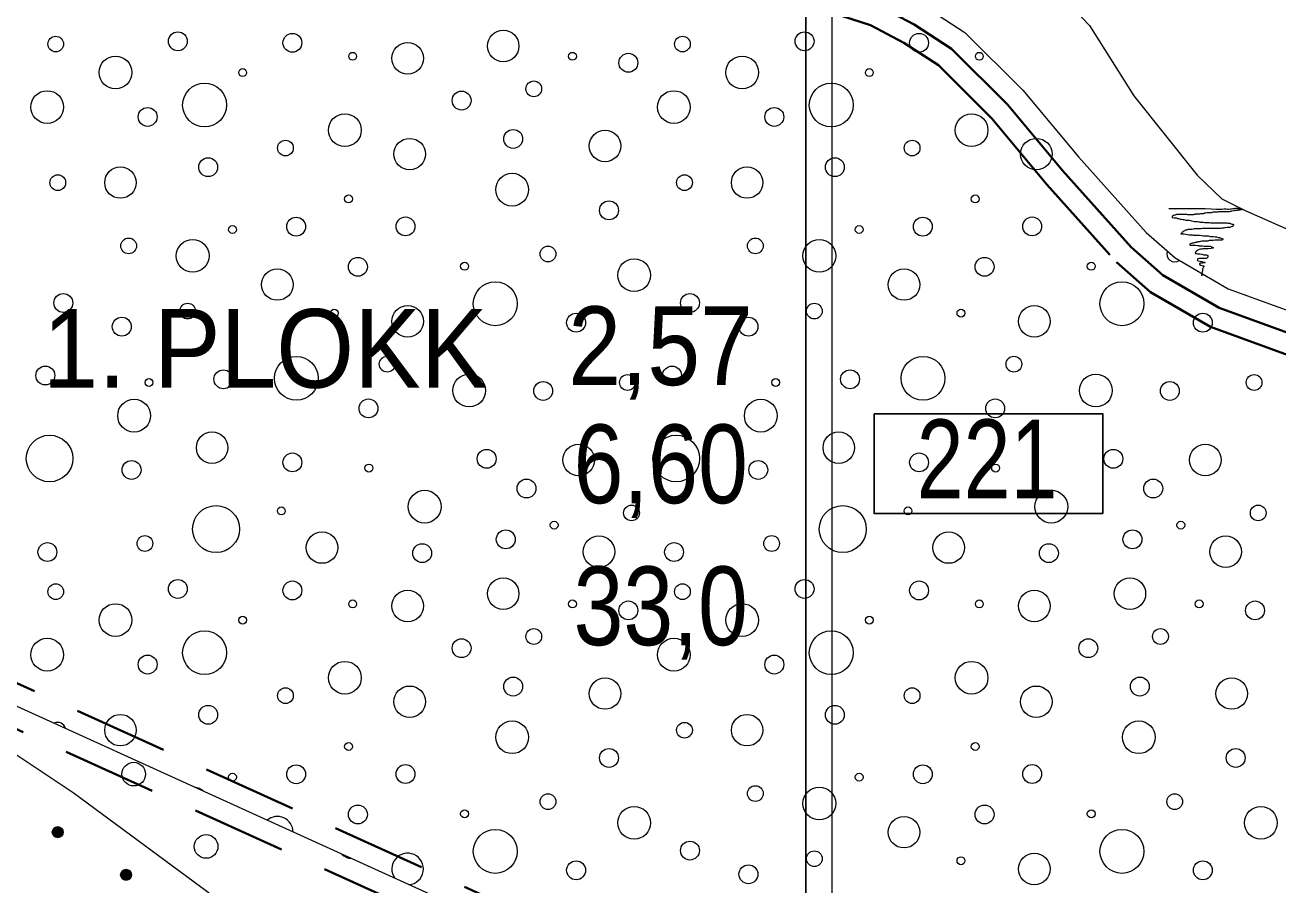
# Model space of a CAD drawing. Extents: x 640104 to 640970, y 6442278 to 6442689.
# Drawn here: x 640265.58 to 640313.3, y 6442396.62 to 6442429.39 of the extents above; entities that cross this region are included whole.
import ezdxf
from ezdxf.enums import TextEntityAlignment as Align

# ---------------------------------------------------------------- set-up
doc = ezdxf.new("R2010")
doc.units = 0
doc.header["$LTSCALE"] = 1.2
doc.linetypes.add('MEDIUM_DASHED', pattern=[4.5, 3, -1.5])
for name, color, linetype, lineweight in [('31', 7, 'Continuous', 13), ('32', 7, 'Continuous', 25), ('33', 7, 'Continuous', 13), ('35', 7, 'Continuous', 35), ('40', 7, 'Continuous', 13), ('41', 7, 'Continuous', 13), ('42', 7, 'Continuous', 13), ('44', 7, 'Continuous', 13)]:
    doc.layers.add(name, color=color, linetype=linetype, lineweight=lineweight)

msp = doc.modelspace()

# ---------------------------------------------------------------- hatches: boundary and pattern name
at = {"layer": '44'}
for points in [[(640267.04, 6442398.634, 1), (640266.62, 6442398.634, 1)], [(640269.643, 6442397.008, 1), (640269.223, 6442397.008, 1)]]:
    msp.add_hatch(color=256, dxfattribs=at).paths.add_polyline_path(points)

# ---------------------------------------------------------------- linework, layer by layer
at = {"layer": '31'}
for points in [[(640262.65, 6442443.97), (640266.43, 6442442.13), (640269.19, 6442440.75), (640271.79, 6442439.65), (640273.4, 6442439.16), (640276.57, 6442438.16), (640280.48, 6442437.11), (640286.11, 6442435.67), (640288.83, 6442435.19), (640292.39, 6442434.88), (640295.32, 6442434.75), (640298.97, 6442433.8), (640301.57, 6442432.68), (640303.79, 6442431.34), (640305.28, 6442430.26), (640306.13, 6442429.37), (640307.82, 6442426.7), (640310.23, 6442423.67), (640311.17, 6442422.77), (640312.06, 6442422.33), (640313.81, 6442421.55)], [(640263.31, 6442441.37), (640267.52, 6442439.33), (640270.41, 6442437.99), (640272.31, 6442437.16), (640275.61, 6442436.16), (640282, 6442434.34), (640286.95, 6442433.35), (640289.44, 6442432.91), (640295.36, 6442431.67), (640296.73, 6442431.41), (640298.41, 6442430.87), (640299.86, 6442430.1), (640301.38, 6442429.11), (640303.59, 6442426.91), (640305.71, 6442424.37), (640308.28, 6442421.49), (640309.39, 6442420.52), (640311.41, 6442419.34), (640315.19, 6442417.97)], [(640139.08, 6442423.82), (640151.96, 6442423.75), (640173.66, 6442421.26), (640213.16, 6442416.61), (640233.94, 6442414.53), (640242.79, 6442413.66), (640295.17, 6442389.83), (640328.15, 6442387.74), (640358.78, 6442385.66), (640377.96, 6442384.87), (640391.41, 6442383.72), (640397.31, 6442383.01), (640414.42, 6442381.45)], [(640256.77, 6442407.3), (640258.78, 6442405.81), (640262.17, 6442403.54), (640264.64, 6442402), (640267.42, 6442400.15), (640272.56, 6442396.35), (640275.54, 6442393.26), (640279.03, 6442388.84), (640281.71, 6442384.42), (640283.58, 6442381.19), (640285.22, 6442377.49), (640286.95, 6442373.22), (640289.01, 6442368.08), (640290.86, 6442364.79), (640293.53, 6442361.19), (640295.32, 6442359.75)]]:
    msp.add_lwpolyline(points, dxfattribs=at)
at = {"layer": '32'}
msp.add_line((640295.32, 6442434.75), (640295.32, 6442359.75), dxfattribs=at)
at = {"layer": '33'}
msp.add_lwpolyline([(640296.32, 6442389.75), (640296.32, 6442431.49), (640295.36, 6442431.67), (640295.32, 6442431.67), (640295.32, 6442389.82)], close=True, dxfattribs=at)
at = {"layer": '33', "lineweight": 25}
msp.add_lwpolyline([(640297.92, 6442414.58), (640306.63, 6442414.58), (640306.63, 6442410.78), (640297.92, 6442410.78)], close=True, dxfattribs=at)
at = {"layer": '35', "lineweight": 40}
msp.add_lwpolyline([(640262.96, 6442440.65), (640267.17, 6442438.61), (640270.08, 6442437.26), (640272.03, 6442436.41), (640275.38, 6442435.39), (640281.81, 6442433.56), (640286.8, 6442432.57), (640289.28, 6442432.13), (640295.2, 6442430.89), (640296.53, 6442430.63), (640298.09, 6442430.13), (640299.45, 6442429.41), (640300.87, 6442428.48), (640303, 6442426.37), (640305.1, 6442423.85), (640307.71, 6442420.93), (640308.92, 6442419.86), (640311.07, 6442418.61), (640314.94, 6442417.21)], dxfattribs=at)
at = {"layer": '35', "linetype": 'MEDIUM_DASHED'}
for points in [[(640262.62, 6442439.93), (640266.83, 6442437.89), (640269.75, 6442436.53), (640271.75, 6442435.66), (640275.16, 6442434.63), (640281.62, 6442432.78), (640286.65, 6442431.78), (640289.13, 6442431.34), (640295.05, 6442430.1), (640296.33, 6442429.86), (640297.78, 6442429.39), (640299.05, 6442428.72), (640300.37, 6442427.86), (640302.41, 6442425.83), (640304.5, 6442423.32), (640307.15, 6442420.36), (640308.45, 6442419.21), (640310.73, 6442417.89), (640314.69, 6442416.45)], [(640153.52, 6442424.38), (640173.75, 6442422.06), (640213.24, 6442417.41), (640234.02, 6442415.33), (640243, 6442414.44), (640295.36, 6442390.62), (640328.2, 6442388.54), (640358.82, 6442386.46), (640378.01, 6442385.67), (640391.49, 6442384.52), (640397.4, 6442383.81), (640411.83, 6442382.49)], [(640153.52, 6442422.77), (640173.56, 6442420.47), (640213.07, 6442415.82), (640233.86, 6442413.74), (640242.58, 6442412.88), (640294.97, 6442389.04), (640328.09, 6442386.94), (640358.73, 6442384.86), (640377.91, 6442384.07), (640391.32, 6442382.92), (640397.23, 6442382.22), (640405.71, 6442381.44)]]:
    msp.add_lwpolyline(points, dxfattribs=at)
at = {"layer": '40'}
for points in [[(640309.15, 6442422.4), (640309.19, 6442422.4), (640309.26, 6442422.4), (640309.33, 6442422.4), (640309.35, 6442422.4), (640309.42, 6442422.4), (640309.52, 6442422.4), (640309.74, 6442422.4), (640309.86, 6442422.4), (640309.88, 6442422.4), (640309.91, 6442422.4), (640309.96, 6442422.4), (640310.01, 6442422.4), (640310.08, 6442422.4), (640310.14, 6442422.4), (640310.18, 6442422.4), (640310.24, 6442422.4), (640310.28, 6442422.4), (640310.33, 6442422.4), (640310.39, 6442422.4), (640310.42, 6442422.4), (640310.47, 6442422.4), (640310.53, 6442422.4), (640310.76, 6442422.39), (640310.96, 6442422.38), (640311.03, 6442422.38), (640311.07, 6442422.38), (640311.09, 6442422.38), (640311.12, 6442422.38), (640311.17, 6442422.38), (640311.24, 6442422.39), (640311.27, 6442422.39), (640311.29, 6442422.39), (640311.31, 6442422.39), (640311.33, 6442422.39), (640311.38, 6442422.38), (640311.4, 6442422.38), (640311.44, 6442422.38), (640311.5, 6442422.39), (640311.54, 6442422.39), (640311.59, 6442422.4), (640311.61, 6442422.4), (640311.66, 6442422.4), (640311.68, 6442422.41), (640311.72, 6442422.41), (640311.75, 6442422.41), (640311.77, 6442422.4), (640311.8, 6442422.4), (640311.83, 6442422.39), (640311.85, 6442422.39)], [(640310.17, 6442422.18), (640310.15, 6442422.17), (640310.11, 6442422.17), (640310.08, 6442422.16), (640310.06, 6442422.16), (640310.04, 6442422.16), (640310, 6442422.16), (640309.97, 6442422.16), (640309.94, 6442422.16), (640309.89, 6442422.16), (640309.87, 6442422.16), (640309.83, 6442422.17), (640309.8, 6442422.17), (640309.78, 6442422.17), (640309.76, 6442422.17), (640309.72, 6442422.17), (640309.69, 6442422.17), (640309.64, 6442422.17), (640309.62, 6442422.17), (640309.6, 6442422.17), (640309.56, 6442422.17), (640309.53, 6442422.17), (640309.5, 6442422.17), (640309.48, 6442422.17), (640309.44, 6442422.17), (640309.41, 6442422.16), (640309.39, 6442422.15), (640309.36, 6442422.15), (640309.33, 6442422.14), (640309.32, 6442422.13), (640309.3, 6442422.12), (640309.28, 6442422.11), (640309.28, 6442422.08), (640309.28, 6442422.06), (640309.35, 6442422.05), (640309.39, 6442422.05), (640309.41, 6442422.04), (640309.44, 6442422.04), (640309.47, 6442422.03), (640309.48, 6442422.02), (640309.52, 6442422.02), (640309.56, 6442422.01), (640309.58, 6442422), (640309.63, 6442421.99), (640309.68, 6442421.98), (640309.72, 6442421.98), (640309.76, 6442421.97), (640309.79, 6442421.96), (640309.84, 6442421.96), (640309.92, 6442421.95)], [(640311.85, 6442422.39), (640311.88, 6442422.38), (640311.91, 6442422.38), (640311.94, 6442422.38), (640311.96, 6442422.36), (640311.94, 6442422.36), (640311.95, 6442422.36), (640311.92, 6442422.36), (640311.89, 6442422.35), (640311.85, 6442422.34), (640311.83, 6442422.34), (640311.8, 6442422.34), (640311.77, 6442422.33), (640311.75, 6442422.33), (640311.73, 6442422.32), (640311.69, 6442422.32), (640311.64, 6442422.31), (640311.62, 6442422.31), (640311.54, 6442422.3), (640311.51, 6442422.29), (640311.48, 6442422.29), (640311.45, 6442422.28), (640311.42, 6442422.28), (640311.4, 6442422.28), (640311.36, 6442422.28), (640311.33, 6442422.28), (640311.26, 6442422.28), (640311.22, 6442422.28), (640311.17, 6442422.28), (640311.12, 6442422.28), (640311.08, 6442422.27), (640311.04, 6442422.27), (640311, 6442422.26), (640310.96, 6442422.26), (640310.85, 6442422.26), (640310.83, 6442422.26), (640310.8, 6442422.25), (640310.76, 6442422.24), (640310.69, 6442422.24), (640310.64, 6442422.23), (640310.6, 6442422.23), (640310.54, 6442422.22), (640310.5, 6442422.22), (640310.47, 6442422.2), (640310.43, 6442422.2), (640310.41, 6442422.2), (640310.39, 6442422.2), (640310.35, 6442422.2), (640310.32, 6442422.19), (640310.29, 6442422.19), (640310.2, 6442422.18), (640310.17, 6442422.18)], [(640309.92, 6442421.95), (640310.01, 6442421.93), (640310.08, 6442421.92), (640310.12, 6442421.91), (640310.18, 6442421.9), (640310.24, 6442421.9), (640310.29, 6442421.89), (640310.33, 6442421.89), (640310.36, 6442421.88), (640310.42, 6442421.88), (640310.46, 6442421.88), (640310.52, 6442421.87), (640310.57, 6442421.87), (640310.62, 6442421.87), (640310.68, 6442421.87), (640310.74, 6442421.86), (640310.78, 6442421.86), (640310.8, 6442421.86), (640310.85, 6442421.86), (640310.9, 6442421.86), (640310.96, 6442421.86), (640311.02, 6442421.86), (640311.08, 6442421.86), (640311.12, 6442421.86), (640311.17, 6442421.86), (640311.2, 6442421.86), (640311.24, 6442421.86), (640311.28, 6442421.86), (640311.32, 6442421.85), (640311.36, 6442421.85), (640311.39, 6442421.84), (640311.48, 6442421.84), (640311.52, 6442421.82), (640311.56, 6442421.8), (640311.59, 6442421.8), (640311.61, 6442421.79), (640311.61, 6442421.76), (640311.6, 6442421.74), (640311.59, 6442421.73), (640311.57, 6442421.72), (640311.56, 6442421.71), (640311.52, 6442421.7), (640311.47, 6442421.68), (640311.37, 6442421.68), (640311.28, 6442421.66), (640311.24, 6442421.65), (640311.17, 6442421.65), (640311.12, 6442421.64), (640311.05, 6442421.64), (640310.96, 6442421.64), (640310.84, 6442421.64), (640310.72, 6442421.64)], [(640310.72, 6442421.64), (640310.67, 6442421.64), (640310.62, 6442421.64), (640310.56, 6442421.64), (640310.52, 6442421.64), (640310.48, 6442421.64), (640310.43, 6442421.64), (640310.37, 6442421.63), (640310.25, 6442421.63), (640310.2, 6442421.63), (640310.16, 6442421.62), (640310.11, 6442421.62), (640310.03, 6442421.6), (640309.94, 6442421.6), (640309.91, 6442421.6), (640309.87, 6442421.6), (640309.85, 6442421.59), (640309.83, 6442421.58), (640309.8, 6442421.58), (640309.78, 6442421.57), (640309.76, 6442421.56), (640309.74, 6442421.55), (640309.7, 6442421.52), (640309.68, 6442421.51), (640309.67, 6442421.49), (640309.64, 6442421.48), (640309.64, 6442421.47), (640309.62, 6442421.45), (640309.61, 6442421.44), (640309.63, 6442421.43), (640309.65, 6442421.43), (640309.69, 6442421.43), (640309.72, 6442421.43), (640309.8, 6442421.42), (640309.85, 6442421.41), (640309.92, 6442421.4), (640310, 6442421.4), (640310.04, 6442421.4), (640310.08, 6442421.38), (640310.12, 6442421.38), (640310.23, 6442421.38), (640310.32, 6442421.38), (640310.39, 6442421.37), (640310.46, 6442421.36), (640310.56, 6442421.36), (640310.65, 6442421.36), (640310.73, 6442421.33), (640310.79, 6442421.33), (640310.85, 6442421.33), (640310.91, 6442421.32)], [(640310.91, 6442421.32), (640310.94, 6442421.32), (640310.97, 6442421.32), (640311.03, 6442421.3), (640311.08, 6442421.29), (640311.11, 6442421.28), (640311.14, 6442421.27), (640311.18, 6442421.26), (640311.2, 6442421.25), (640311.2, 6442421.22), (640311.19, 6442421.21), (640311.17, 6442421.2), (640311.15, 6442421.2), (640311.07, 6442421.19), (640311.03, 6442421.19), (640311, 6442421.19), (640310.96, 6442421.19), (640310.9, 6442421.19), (640310.84, 6442421.18), (640310.81, 6442421.18), (640310.78, 6442421.18), (640310.69, 6442421.18), (640310.64, 6442421.16), (640310.62, 6442421.16), (640310.58, 6442421.16), (640310.56, 6442421.16), (640310.52, 6442421.16), (640310.46, 6442421.16), (640310.41, 6442421.15), (640310.36, 6442421.14), (640310.32, 6442421.13), (640310.29, 6442421.13), (640310.26, 6442421.13), (640310.24, 6442421.12), (640310.2, 6442421.12), (640310.19, 6442421.11), (640310.15, 6442421.1), (640310.13, 6442421.09), (640310.11, 6442421.09), (640310.08, 6442421.08), (640310.04, 6442421.08), (640310, 6442421.07), (640309.96, 6442421.05), (640309.95, 6442421.04), (640309.95, 6442421), (640309.97, 6442421), (640310.02, 6442421), (640310.08, 6442421), (640310.14, 6442421), (640310.17, 6442421), (640310.24, 6442420.99), (640310.28, 6442420.99)], [(640310.28, 6442420.99), (640310.29, 6442420.98), (640310.32, 6442420.98), (640310.36, 6442420.98), (640310.4, 6442420.98), (640310.43, 6442420.98), (640310.5, 6442420.97), (640310.56, 6442420.97), (640310.58, 6442420.97), (640310.61, 6442420.97), (640310.64, 6442420.97), (640310.68, 6442420.97), (640310.72, 6442420.96), (640310.75, 6442420.95), (640310.78, 6442420.94), (640310.81, 6442420.93), (640310.84, 6442420.92), (640310.84, 6442420.89), (640310.76, 6442420.88), (640310.65, 6442420.87), (640310.61, 6442420.87), (640310.54, 6442420.86), (640310.5, 6442420.86), (640310.45, 6442420.86), (640310.4, 6442420.85), (640310.36, 6442420.85), (640310.31, 6442420.84), (640310.25, 6442420.81), (640310.24, 6442420.8), (640310.2, 6442420.78), (640310.19, 6442420.76), (640310.17, 6442420.75), (640310.16, 6442420.72), (640310.15, 6442420.7), (640310.16, 6442420.69), (640310.2, 6442420.68), (640310.24, 6442420.67), (640310.33, 6442420.67), (640310.4, 6442420.66), (640310.44, 6442420.65), (640310.48, 6442420.64), (640310.52, 6442420.64), (640310.58, 6442420.64), (640310.64, 6442420.61), (640310.64, 6442420.58), (640310.64, 6442420.56), (640310.63, 6442420.54), (640310.58, 6442420.5), (640310.56, 6442420.49), (640310.52, 6442420.49), (640310.46, 6442420.49), (640310.4, 6442420.49), (640310.36, 6442420.49), (640310.3, 6442420.49), (640310.24, 6442420.48), (640310.24, 6442420.45), (640310.23, 6442420.44), (640310.24, 6442420.42), (640310.26, 6442420.41), (640310.34, 6442420.39), (640310.4, 6442420.38), (640310.43, 6442420.37), (640310.47, 6442420.36), (640310.51, 6442420.36), (640310.53, 6442420.34), (640310.52, 6442420.33), (640310.48, 6442420.33), (640310.43, 6442420.32), (640310.36, 6442420.32), (640310.34, 6442420.32), (640310.32, 6442420.31), (640310.32, 6442420.28), (640310.33, 6442420.26), (640310.35, 6442420.25), (640310.37, 6442420.24), (640310.4, 6442420.23), (640310.44, 6442420.22), (640310.48, 6442420.21), (640310.48, 6442420.18), (640310.47, 6442420.16), (640310.46, 6442420.14), (640310.44, 6442420.12), (640310.43, 6442420.1), (640310.43, 6442420.07), (640310.43, 6442420.04), (640310.43, 6442420.01), (640310.42, 6442419.99), (640310.42, 6442419.96), (640310.41, 6442419.94), (640310.4, 6442419.91), (640310.4, 6442419.88), (640310.4, 6442419.85), (640310.4, 6442419.84), (640310.4, 6442419.87)]]:
    msp.add_lwpolyline(points, dxfattribs=at)
at = {"layer": '41'}
for centre, radius in [((640266.753, 6442428.667), 0.3), ((640271.405, 6442428.772), 0.36), ((640275.766, 6442428.715), 0.36), ((640283.797, 6442428.592), 0.6), ((640290.622, 6442428.667), 0.3), ((640295.274, 6442428.772), 0.36), ((640299.635, 6442428.715), 0.36), ((640280.155, 6442428.124), 0.6), ((640269.029, 6442427.586), 0.624), ((640278.061, 6442428.202), 0.15), ((640286.434, 6442428.202), 0.15), ((640288.563, 6442427.955), 0.36), ((640292.898, 6442427.586), 0.624), ((640301.93, 6442428.202), 0.15), ((640273.873, 6442427.581), 0.15), ((640297.742, 6442427.581), 0.15), ((640272.421, 6442426.343), 0.835), ((640284.961, 6442426.96), 0.3), ((640296.29, 6442426.343), 0.835), ((640266.427, 6442426.266), 0.624), ((640282.212, 6442426.514), 0.36), ((640290.296, 6442426.266), 0.624), ((640270.253, 6442425.89), 0.36), ((640277.767, 6442425.388), 0.624), ((640294.122, 6442425.89), 0.36), ((640301.636, 6442425.388), 0.624), ((640280.233, 6442424.473), 0.6), ((640284.176, 6442425.052), 0.36), ((640287.676, 6442424.785), 0.6), ((640304.102, 6442424.473), 0.6), ((640275.502, 6442424.704), 0.3), ((640299.371, 6442424.704), 0.3), ((640272.56, 6442423.976), 0.36), ((640296.429, 6442423.976), 0.36), ((640266.831, 6442423.387), 0.3), ((640269.217, 6442423.39), 0.6), ((640284.135, 6442423.119), 0.624), ((640290.7, 6442423.387), 0.3), ((640293.086, 6442423.39), 0.6), ((640277.905, 6442422.766), 0.15), ((640287.826, 6442422.331), 0.36), ((640301.774, 6442422.766), 0.15), ((640273.486, 6442421.599), 0.15), ((640275.909, 6442421.709), 0.36), ((640280.076, 6442421.719), 0.36), ((640297.355, 6442421.599), 0.15), ((640299.778, 6442421.709), 0.36), ((640303.945, 6442421.719), 0.36), ((640269.529, 6442420.975), 0.3), ((640293.398, 6442420.975), 0.3), ((640271.968, 6442420.595), 0.624), ((640285.504, 6442420.666), 0.3), ((640295.837, 6442420.595), 0.624), ((640278.262, 6442420.178), 0.36), ((640282.324, 6442420.201), 0.15), ((640288.786, 6442419.859), 0.624), ((640302.131, 6442420.178), 0.36), ((640306.193, 6442420.201), 0.15), ((640275.193, 6442419.502), 0.6), ((640299.062, 6442419.502), 0.6), ((640283.494, 6442418.772), 0.838), ((640307.363, 6442418.772), 0.838), ((640267.041, 6442418.801), 0.36), ((640290.91, 6442418.801), 0.36), ((640271.776, 6442418.491), 0.3), ((640277.362, 6442418.413), 0.15), ((640280.155, 6442418.101), 0.6), ((640286.573, 6442418.05), 0.36), ((640295.645, 6442418.491), 0.3), ((640301.231, 6442418.413), 0.15), ((640304.024, 6442418.101), 0.6), ((640310.442, 6442418.05), 0.36), ((640269.268, 6442417.898), 0.36), ((640293.137, 6442417.898), 0.36), ((640275.92, 6442415.931), 0.834), ((640279.378, 6442416.469), 0.3), ((640299.789, 6442415.931), 0.834), ((640303.247, 6442416.469), 0.3), ((640266.357, 6442416.035), 0.36), ((640273.137, 6442415.892), 0.36), ((640282.5, 6442415.463), 0.624), ((640288.528, 6442415.77), 0.3), ((640290.226, 6442416.035), 0.36), ((640297.006, 6442415.892), 0.36), ((640306.369, 6442415.463), 0.624), ((640312.397, 6442415.77), 0.3), ((640270.306, 6442415.77), 0.15), ((640285.319, 6442415.448), 0.36), ((640294.175, 6442415.77), 0.15), ((640309.188, 6442415.448), 0.36), ((640269.737, 6442414.506), 0.624), ((640278.665, 6442414.783), 0.36), ((640293.606, 6442414.506), 0.624), ((640302.534, 6442414.783), 0.36), ((640266.517, 6442412.874), 0.889), ((640272.709, 6442413.286), 0.6), ((640290.386, 6442412.874), 0.889), ((640296.578, 6442413.286), 0.6), ((640283.166, 6442412.862), 0.36), ((640286.668, 6442412.818), 0.6), ((640307.035, 6442412.862), 0.36), ((640310.537, 6442412.818), 0.6), ((640269.642, 6442412.438), 0.36), ((640275.766, 6442412.725), 0.36), ((640278.682, 6442412.509), 0.15), ((640293.511, 6442412.438), 0.36), ((640299.635, 6442412.725), 0.36), ((640302.551, 6442412.509), 0.15), ((640284.685, 6442411.73), 0.36), ((640308.554, 6442411.73), 0.36), ((640280.804, 6442411.038), 0.624), ((640304.673, 6442411.038), 0.624), ((640272.86, 6442410.184), 0.893), ((640275.346, 6442410.877), 0.15), ((640288.684, 6442410.799), 0.3), ((640296.729, 6442410.184), 0.893), ((640299.215, 6442410.877), 0.15), ((640312.553, 6442410.799), 0.3), ((640285.738, 6442410.334), 0.15), ((640309.607, 6442410.334), 0.15), ((640270.15, 6442409.635), 0.3), ((640276.897, 6442409.479), 0.6), ((640283.893, 6442409.793), 0.36), ((640287.442, 6442409.323), 0.6), ((640294.019, 6442409.635), 0.3), ((640300.766, 6442409.479), 0.6), ((640307.762, 6442409.793), 0.36), ((640311.311, 6442409.323), 0.6), ((640266.435, 6442409.309), 0.36), ((640280.711, 6442409.267), 0.36), ((640290.304, 6442409.309), 0.36), ((640304.58, 6442409.267), 0.36), ((640266.753, 6442407.798), 0.3), ((640271.405, 6442407.903), 0.36), ((640275.766, 6442407.846), 0.36), ((640283.797, 6442407.723), 0.6), ((640290.622, 6442407.798), 0.3), ((640295.274, 6442407.903), 0.36), ((640299.635, 6442407.846), 0.36), ((640307.666, 6442407.723), 0.6), ((640278.061, 6442407.333), 0.15), ((640280.155, 6442407.255), 0.6), ((640286.434, 6442407.333), 0.15), ((640288.563, 6442407.086), 0.36), ((640301.93, 6442407.333), 0.15), ((640304.024, 6442407.255), 0.6), ((640310.303, 6442407.333), 0.15), ((640312.432, 6442407.086), 0.36), ((640269.029, 6442406.717), 0.624), ((640292.898, 6442406.717), 0.624), ((640273.873, 6442406.712), 0.15), ((640297.742, 6442406.712), 0.15), ((640266.427, 6442405.397), 0.624), ((640272.421, 6442405.474), 0.835), ((640282.212, 6442405.645), 0.36), ((640284.961, 6442406.091), 0.3), ((640290.296, 6442405.397), 0.624), ((640296.29, 6442405.474), 0.835), ((640306.081, 6442405.645), 0.36), ((640308.83, 6442406.091), 0.3), ((640270.253, 6442405.021), 0.36), ((640277.767, 6442404.519), 0.624), ((640294.122, 6442405.021), 0.36), ((640301.636, 6442404.519), 0.624), ((640284.176, 6442404.183), 0.36), ((640308.045, 6442404.183), 0.36), ((640275.502, 6442403.835), 0.3), ((640280.233, 6442403.604), 0.6), ((640287.676, 6442403.916), 0.6), ((640299.371, 6442403.835), 0.3), ((640304.102, 6442403.604), 0.6), ((640311.545, 6442403.916), 0.6), ((640269.217, 6442402.521), 0.6), ((640272.56, 6442403.107), 0.36), ((640293.086, 6442402.521), 0.6), ((640296.429, 6442403.107), 0.36), ((640284.135, 6442402.25), 0.624), ((640290.7, 6442402.518), 0.3), ((640308.004, 6442402.25), 0.624), ((640277.905, 6442401.897), 0.15), ((640287.826, 6442401.462), 0.36), ((640301.774, 6442401.897), 0.15), ((640311.695, 6442401.462), 0.36), ((640275.909, 6442400.84), 0.36), ((640280.076, 6442400.85), 0.36), ((640299.778, 6442400.84), 0.36), ((640303.945, 6442400.85), 0.36), ((640273.486, 6442400.73), 0.15), ((640297.355, 6442400.73), 0.15), ((640293.398, 6442400.106), 0.3), ((640295.837, 6442399.726), 0.624), ((640285.504, 6442399.797), 0.3), ((640309.373, 6442399.797), 0.3), ((640278.262, 6442399.309), 0.36), ((640282.324, 6442399.332), 0.15), ((640288.786, 6442398.99), 0.624), ((640302.131, 6442399.309), 0.36), ((640306.193, 6442399.332), 0.15), ((640312.655, 6442398.99), 0.624), ((640299.062, 6442398.633), 0.6), ((640283.494, 6442397.903), 0.838), ((640307.363, 6442397.903), 0.838), ((640290.91, 6442397.932), 0.36), ((640295.645, 6442397.622), 0.3), ((640286.573, 6442397.181), 0.36), ((640293.137, 6442397.029), 0.36), ((640301.231, 6442397.544), 0.15), ((640304.024, 6442397.232), 0.6), ((640310.442, 6442397.181), 0.36)]:
    msp.add_circle(centre, radius, dxfattribs=at)
for centre, radius, start, end in [((640309.373, 6442420.666), 0.3, 158.7243, 305.7501), ((640266.831, 6442402.518), 0.3, 13.4438, 117.6263), ((640271.968, 6442399.726), 0.624, 48.9535, 82.1166), ((640275.193, 6442398.633), 0.6, 0.9496, 130.1205), ((640280.155, 6442397.232), 0.6, 275.031, 216.0391)]:
    msp.add_arc(centre, radius, start, end, dxfattribs=at)
at = {"layer": '42'}
for centre in [(640269.723, 6442400.846), (640272.48, 6442398.089)]:
    msp.add_circle(centre, 0.45, dxfattribs=at)
msp.add_arc((640277.996, 6442398.089), 0.45, 220.6896, 270.3805, dxfattribs=at)
at = {"layer": '44'}
for centre in [(640266.83, 6442398.634), (640269.433, 6442397.008)]:
    msp.add_circle(centre, 0.21, dxfattribs=at)

# ---------------------------------------------------------------- texts
at = {"layer": '33'}
for s, width, p in [('2,57', 0.9, (640289.79, 6442415.67)), ('6,60', 0.85, (640289.795, 6442411.17)), ('221', 0.8, (640302.225, 6442411.36)), ('33,0', 0.85, (640289.795, 6442405.76))]:
    msp.add_text(s, height=3, dxfattribs=dict(at, width=width)).set_placement(p, align=Align.CENTER)
at = {"layer": '35', "width": 0.95}
msp.add_text('1. PLOKK', height=3, dxfattribs=at).set_placement((640274.725, 6442415.57), align=Align.CENTER)

doc.saveas('drawing.dxf')
